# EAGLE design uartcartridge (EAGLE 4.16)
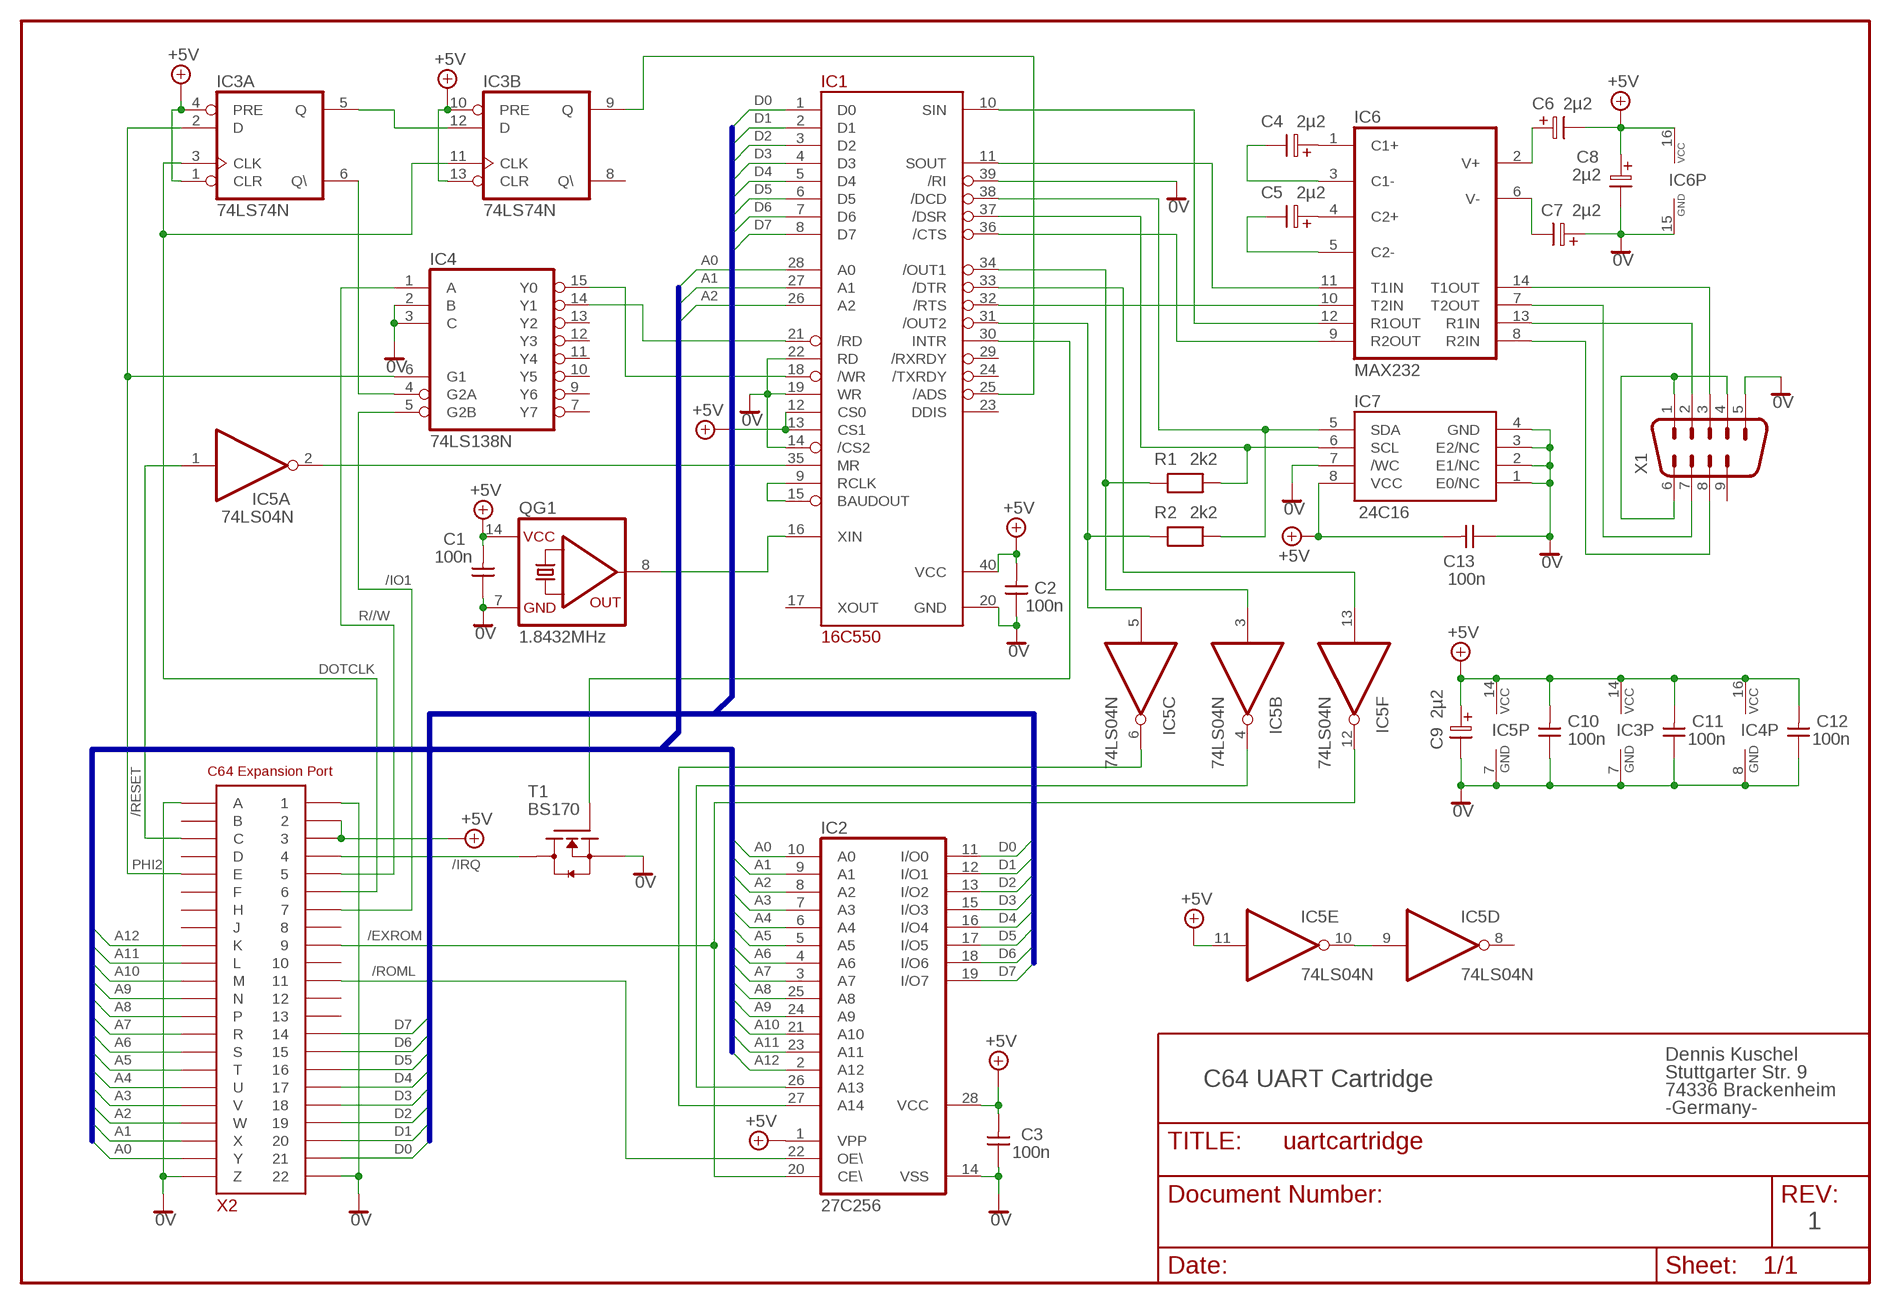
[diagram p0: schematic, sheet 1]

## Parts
C1  100n  CAPNP-5  [C-5]
C2  100n  CAPNP-5  [C-5]
C3  100n  CAPNP-5  [C-5]
C4  2µ2  ELC-2,5  [ES-2,5]
C5  2µ2  ELC-2,5  [ES-2,5]
C6  2µ2  ELC-2,5  [ES-2,5]
C7  2µ2  ELC-2,5  [ES-2,5]
C8  2µ2  ELC-2,5  [ES-2,5]
C9  2µ2  ELC-2,5  [ES-2,5]
C10  100n  CAPNP-5  [C-5]
C11  100n  CAPNP-5  [C-5]
C12  100n  CAPNP-5  [C-5]
C13  100n  CAPNP-5  [C-5]
IC1  16C550  [DIL40]
IC2  27C256  27C256AG  [DIL28-6]
IC3  74LS74N  [DIL14]
IC4  74LS138N  [DIL16]
IC5  74LS04N  [DIL14]
IC6  MAX232  [DIL16]
IC7  24C16  [DIL8]
QG1  1.8432MHz  QG5860  [DIL14S]
R1  2k2  RESEU-7,5  [R-7,5]
R2  2k2  RESEU-7,5  [R-7,5]
T1  BS170  BS170B  [TO92-]
X1  M09D  [M09D]
X2  CARTRIDGE-SUBD9  [EXPBOARD-SER]

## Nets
0V: C1.1 C2.1 C3.1 C7.1 C8.2 C9.2 C10.1 C11.1 C12.1 C13.1 IC1.14(/CS2) IC1.19(WR) IC1.20(GND) IC1.22(RD) IC1.39(/RI) IC2.14(VSS) IC3.7(P:GND) IC4.2(B) IC4.3(C) IC4.8(GND) IC5.7(P:GND) IC6.15(GND) IC7.1(E0/NC) IC7.2(E1/NC) IC7.3(E2/NC) IC7.4(GND) IC7.7(/WC) QG1.7(GND) T1.1(S) X1.5 X2.P$1 X2.P$22 X2.P$23(A) X2.P$44(Z)
+5V: C1.2 C2.2 C3.2 C6.2 C8.1 C9.1 C10.2 C11.2 C12.2 C13.2 IC1.12(CS0) IC1.13(CS1) IC1.40(VCC) IC2.1(VPP) IC2.28(VCC) IC3.1(A:CLR) IC3.4(A:PRE) IC3.10(B:PRE) IC3.13(B:CLR) IC3.14(P:VCC) IC4.16(VCC) IC5.11(E:I) IC5.14(P:VCC) IC6.16(VCC) IC7.8(VCC) QG1.14(VCC) X2.P$2 X2.P$3
/EXROM: IC2.20(CE\) IC5.12(F:O) X2.P$9
/IO1: IC4.5(G2B) X2.P$7
/IRQ: T1.3(D) X2.P$4
/RESET: IC5.1(A:I) X2.P$25(C)
/ROML: IC2.22(OE\) X2.P$11
A0: IC1.28(A0) IC2.10(A0) X2.P$43(Y)
A1: IC1.27(A1) IC2.9(A1) X2.P$42(X)
A2: IC1.26(A2) IC2.8(A2) X2.P$41(W)
A3: IC2.7(A3) X2.P$40(V)
A4: IC2.6(A4) X2.P$39(U)
A5: IC2.5(A5) X2.P$38(T)
A6: IC2.4(A6) X2.P$37(S)
A7: IC2.3(A7) X2.P$36(R)
A8: IC2.25(A8) X2.P$35(P)
A9: IC2.24(A9) X2.P$34(N)
A10: IC2.21(A10) X2.P$33(M)
A11: IC2.23(A11) X2.P$32(L)
A12: IC2.2(A12) X2.P$31(K)
CTS: IC6.8(R2IN) X1.8
D0: IC1.1(D0) IC2.11(I/O0) X2.P$21
D1: IC1.2(D1) IC2.12(I/O1) X2.P$20
D2: IC1.3(D2) IC2.13(I/O2) X2.P$19
D3: IC1.4(D3) IC2.15(I/O3) X2.P$18
D4: IC1.5(D4) IC2.16(I/O4) X2.P$17
D5: IC1.6(D5) IC2.17(I/O5) X2.P$16
D6: IC1.7(D6) IC2.18(I/O6) X2.P$15
D7: IC1.8(D7) IC2.19(I/O7) X2.P$14
DOTCLK: IC3.3(A:CLK) IC3.11(B:CLK) X2.P$6
N$1: IC3.5(A:Q) IC3.12(B:D)
N$2: IC1.25(/ADS) IC3.9(B:Q)
N$3: IC3.6(A:Q\) IC4.4(G2A)
N$4: IC1.21(/RD) IC4.14(Y1)
N$5: IC1.18(/WR) IC4.15(Y0)
N$6: IC5.9(D:I) IC5.10(E:O)
N$7: IC1.33(/DTR) IC5.13(F:I)
N$8: IC1.9(RCLK) IC1.15(BAUDOUT)
N$9: IC1.16(XIN) QG1.8(OUT)
N$10: IC1.34(/OUT1) IC5.3(B:I) R1.1
N$11: IC1.35(MR) IC5.2(A:O)
N$12: IC1.31(/OUT2) IC5.5(C:I) R2.1
N$13: IC2.26(A13) IC5.4(B:O)
N$14: IC2.27(A14) IC5.6(C:O)
N$15: C4.1 IC6.1(C1+)
N$16: IC1.30(INTR) T1.2(G)
N$17: C5.1 IC6.4(C2+)
N$18: C7.2 IC6.6(V-)
N$19: C6.1 IC6.2(V+)
N$20: C4.2 IC6.3(C1-)
N$21: C5.2 IC6.5(C2-)
N$22: IC1.10(SIN) IC6.12(R1OUT)
N$23: IC1.11(SOUT) IC6.11(T1IN)
N$24: IC1.32(/RTS) IC6.10(T2IN)
N$25: IC1.36(/CTS) IC6.9(R2OUT)
N$26: X1.1 X1.4 X1.6
N$27: IC1.37(/DSR) IC7.6(SCL) R1.2
N$29: IC1.38(/DCD) IC7.5(SDA) R2.2
PHI2: IC3.2(A:D) IC4.6(G1) X2.P$27(E)
R//W: IC4.1(A) X2.P$5
RTS: IC6.7(T2OUT) X1.7
RXD: IC6.13(R1IN) X1.2
TXD: IC6.14(T1OUT) X1.3
Unconnected: IC1.17(XOUT) IC1.23(DDIS) IC1.24(/TXRDY) IC1.29(/RXRDY) IC3.8(B:Q\) IC4.7(Y7) IC4.9(Y6) IC4.10(Y5) IC4.11(Y4) IC4.12(Y3) IC4.13(Y2) IC5.8(D:O) X1.9 X2.P$8 X2.P$10 X2.P$12 X2.P$13 X2.P$24(B) X2.P$26(D) X2.P$28(F) X2.P$29(H) X2.P$30(J)

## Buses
D[0..7]
A[0..12]

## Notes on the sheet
- C64 Expansion Port
- Dennis Kuschel
- Stuttgarter Str. 9
- C64 UART Cartridge
- 74336 Brackenheim
- -Germany-
- 1

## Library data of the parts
C1-C3 C10-C13 = discrete-my:CAPNP-5
C4-C9 = discrete-my:ELC-2,5
IC1 = UART:16C550: UART 16C550
IC2 = memory:27C256AG: MEMORY
IC3 = 74ttl:74*74: Dual D type positive edge triggered FLIP FLOP, preset and clear
IC4 = 74ttl:74*138: 3-line to 8-line DECODER/DEMULTIPLEXER
IC5 = 74ttl:74*04: Hex INVERTER
IC6 = maxim:MAX232: RS232 TRANSEIVER
IC7 = miscic:24C16
QG1 = crystal:QG5860: CRYSTAL RESONATOR
R1 R2 = discrete-my:RESEU-7,5
T1 = transistor-fet:BS170
X1 = con-subd_my:M09: SUB-D
X2 = c64:CARTRIDGE-SUBD9

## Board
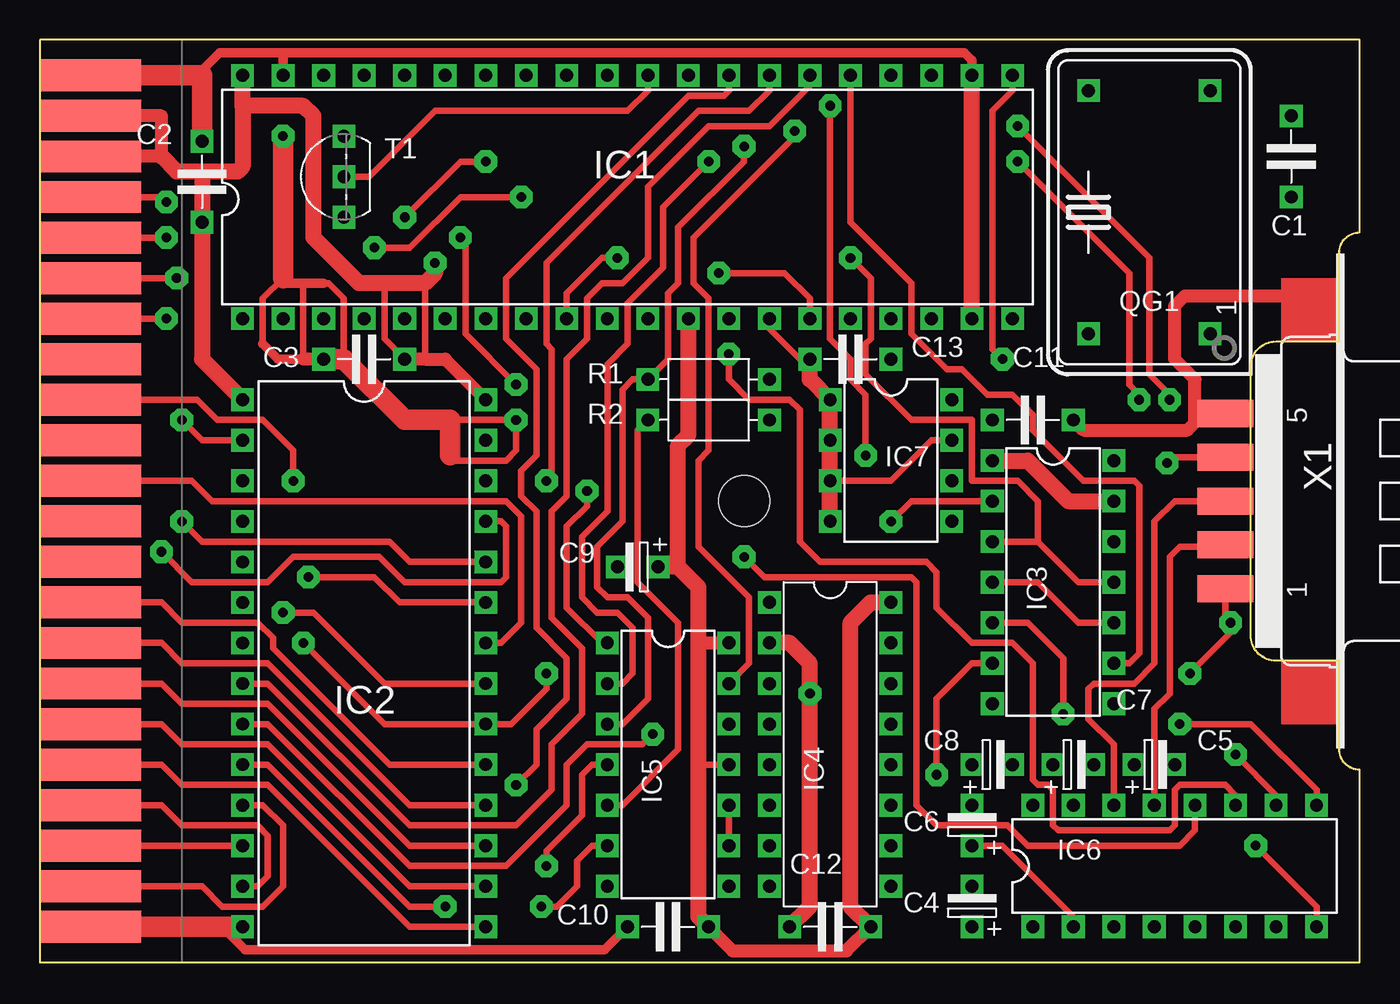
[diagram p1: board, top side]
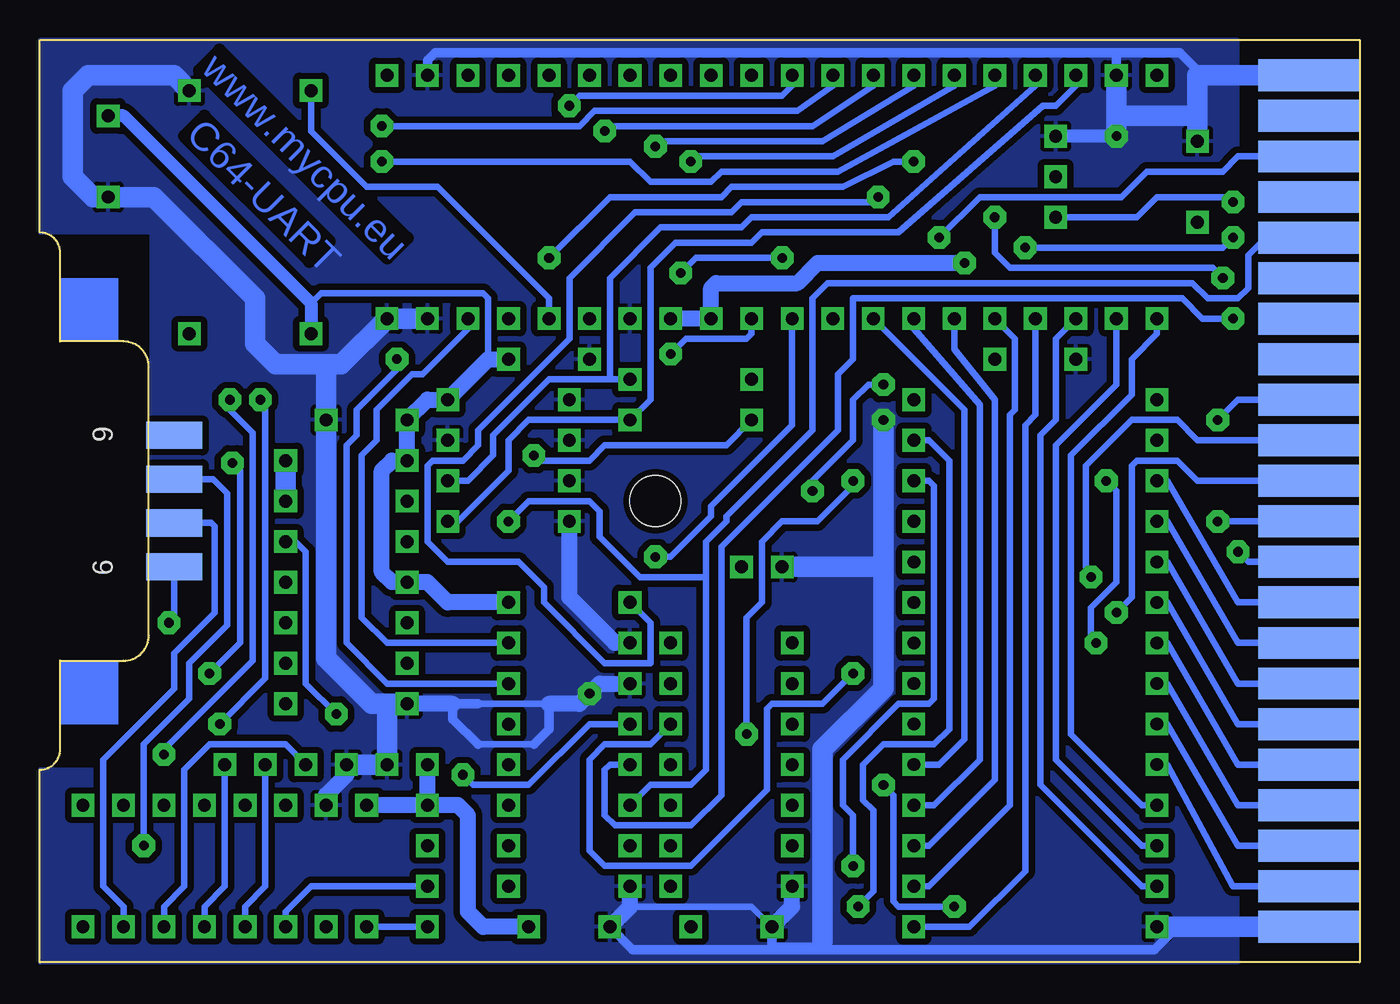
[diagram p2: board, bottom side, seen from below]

Size 82.71 x 57.78 mm. Coordinates in mm from the lower left corner, seen from the top.
Copper layers (1*16): Top 0.035mm / dielectric 1.5mm / Bottom 0.035mm
Design rules "default": minimum track width 10mil, minimum drill 0.6mm, track to track 10mil, track to pad 8mil, pad to pad 8mil, via to via 8mil, smd to smd 8mil, copper to edge 0mil, drill to drill 8mil, minimum pad ring 10mil, minimum via ring 8mil, stop-mask expansion 4mil, vias tented up to drill 0mil, thermal gap 10mil

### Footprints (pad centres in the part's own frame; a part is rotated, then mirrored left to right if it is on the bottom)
C-5 = drill 0.813 pad 1.422 square: 1 -2.54,0; 2 2.54,0
ES-2,5 = drill 0.813 pad 1.422 square: 1 -1.27,0; 2 1.27,0
DIL40 = drill 0.813 pad 1.422 square: 1 -24.13,-7.62; 2 -21.59,-7.62; 3 -19.05,-7.62; 4 -16.51,-7.62; 5 -13.97,-7.62; 6 -11.43,-7.62; 7 -8.89,-7.62; 8 -6.35,-7.62; 9 -3.81,-7.62; 10 -1.27,-7.62; 11 1.27,-7.62; 12 3.81,-7.62; 13 6.35,-7.62; 14 8.89,-7.62; 15 11.43,-7.62; 16 13.97,-7.62; 17 16.51,-7.62; 18 19.05,-7.62; 19 21.59,-7.62; 20 24.13,-7.62; 21 24.13,7.62; 22 21.59,7.62; 23 19.05,7.62; 24 16.51,7.62; 25 13.97,7.62; 26 11.43,7.62; 27 8.89,7.62; 28 6.35,7.62; 29 3.81,7.62; 30 1.27,7.62; 31 -1.27,7.62; 32 -3.81,7.62; 33 -6.35,7.62; 34 -8.89,7.62; 35 -11.43,7.62; 36 -13.97,7.62; 37 -16.51,7.62; 38 -19.05,7.62; 39 -21.59,7.62; 40 -24.13,7.62
DIL28-6 = drill 0.8 pad 1.422 square: 1 -16.51,-7.62; 2 -13.97,-7.62; 3 -11.43,-7.62; 4 -8.89,-7.62; 5 -6.35,-7.62; 6 -3.81,-7.62; 7 -1.27,-7.62; 8 1.27,-7.62; 9 3.81,-7.62; 10 6.35,-7.62; 11 8.89,-7.62; 12 11.43,-7.62; 13 13.97,-7.62; 14 16.51,-7.62; 15 16.51,7.62; 16 13.97,7.62; 17 11.43,7.62; 18 8.89,7.62; 19 6.35,7.62; 20 3.81,7.62; 21 1.27,7.62; 22 -1.27,7.62; 23 -3.81,7.62; 24 -6.35,7.62; 25 -8.89,7.62; 26 -11.43,7.62; 27 -13.97,7.62; 28 -16.51,7.62
DIL14 = drill 0.813 pad 1.422 square: 1 -7.62,-3.81; 2 -5.08,-3.81; 3 -2.54,-3.81; 4 0,-3.81; 5 2.54,-3.81; 6 5.08,-3.81; 7 7.62,-3.81; 8 7.62,3.81; 9 5.08,3.81; 10 2.54,3.81; 11 0,3.81; 12 -2.54,3.81; 13 -5.08,3.81; 14 -7.62,3.81
DIL16 = drill 0.813 pad 1.422 square: 1 -8.89,-3.81; 2 -6.35,-3.81; 3 -3.81,-3.81; 4 -1.27,-3.81; 5 1.27,-3.81; 6 3.81,-3.81; 7 6.35,-3.81; 8 8.89,-3.81; 9 8.89,3.81; 10 6.35,3.81; 11 3.81,3.81; 12 1.27,3.81; 13 -1.27,3.81; 14 -3.81,3.81; 15 -6.35,3.81; 16 -8.89,3.81
DIL16' = drill 0.8 pad 1.422 square: 1 -8.89,-3.81; 2 -6.35,-3.81; 3 -3.81,-3.81; 4 -1.27,-3.81; 5 1.27,-3.81; 6 3.81,-3.81; 7 6.35,-3.81; 8 8.89,-3.81; 9 8.89,3.81; 10 6.35,3.81; 11 3.81,3.81; 12 1.27,3.81; 13 -1.27,3.81; 14 -3.81,3.81; 15 -6.35,3.81; 16 -8.89,3.81
DIL8 = drill 0.8 pad 1.422 square: 1 -3.81,-3.81; 2 -1.27,-3.81; 3 1.27,-3.81; 4 3.81,-3.81; 5 3.81,3.81; 6 1.27,3.81; 7 -1.27,3.81; 8 -3.81,3.81
DIL14S = drill 0.813 pad 1.422 square: 1 -7.62,-3.81; 7 7.62,-3.81; 8 7.62,3.81; 14 -7.62,3.81
R-7,5 = drill 0.813 pad 1.422 square: 1 -3.81,0; 2 3.81,0
TO92- = drill 0.8 pad 1.422 square: 1 2.54,0; 2 0,0; 3 -2.54,0
M09D = smd 1.7 x 3.5: 1 5.486,-6.045; 2 2.743,-6.045; 3 0,-6.045; 4 -2.743,-6.045; 5 -5.486,-6.045 | smd 1.7 x 3.5 bottom: 6 4.115,-6.045; 7 1.372,-6.045; 8 -1.372,-6.045; 9 -4.115,-6.045
EXPBOARD-SER = smd 6.35 x 2: P$1 3.175,55.88; P$2 3.175,53.34; P$3 3.175,50.8; P$4 3.175,48.26; P$5 3.175,45.72; P$6 3.175,43.18; P$7 3.175,40.64; P$8 3.175,38.1; P$9 3.175,35.56; P$10 3.175,33.02; P$11 3.175,30.48; P$12 3.175,27.94; P$13 3.175,25.4; P$14 3.175,22.86; P$15 3.175,20.32; P$16 3.175,17.78; P$17 3.175,15.24; P$18 3.175,12.7; P$19 3.175,10.16; P$20 3.175,7.62; P$21 3.175,5.08; P$22 3.175,2.54 | smd 6.35 x 2 bottom: P$23 3.175,55.88; P$24 3.175,53.34; P$25 3.175,50.8; P$26 3.175,48.26; P$27 3.175,45.72; P$28 3.175,43.18; P$29 3.175,40.64; P$30 3.175,38.1; P$31 3.175,35.56; P$32 3.175,33.02; P$33 3.175,30.48; P$34 3.175,27.94; P$35 3.175,25.4; P$36 3.175,22.86; P$37 3.175,20.32; P$38 3.175,17.78; P$39 3.175,15.24; P$40 3.175,12.7; P$41 3.175,10.16; P$42 3.175,7.62; P$43 3.175,5.08; P$44 3.175,2.54 | hole 3.2: 44.133,29.21

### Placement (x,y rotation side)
C1  78.42,50.48 90 top
C2  10.16,48.89 270 top
C3  20.32,37.78 0 top
C4  58.42,3.49 90 top
C5  69.85,12.38 0 top
C6  58.42,8.57 90 top
C7  64.77,12.38 0 top
C8  59.69,12.38 0 top
C9  37.47,24.77 180 top
C10  39.37,2.22 0 top
C11  62.23,33.97 180 top
C12  49.53,2.22 0 top
C13  50.8,37.78 0 top
IC1  36.83,47.94 0 top
IC2  20.32,18.73 270 top
IC3  63.5,23.81 270 top
IC4  49.53,13.65 270 top
IC5  39.37,12.38 270 top
IC6  MAX232  [DIL16']  71.12,6.03 0 top
IC7  53.34,31.43 270 top
QG1  69.53,46.99 90 top
R1  41.91,36.51 0 top
R2  41.91,33.97 0 top
T1  19.05,49.21 90 top
X1  80.33,28.89 270 top
X2  0,-0.32 0 top

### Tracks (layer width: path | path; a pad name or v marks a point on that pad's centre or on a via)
0V  (via drill 0.6 pad 1.42)
  Top 0.406: 15.24,42.54 15.24,42.86 13.97,41.59 13.97,38.74 | 16.51,37.78 16.51,42.54 | 25.72,31.75 25.72,31.43 29.21,31.43 29.84,32.07 v29.84,33.97 25.72,33.97 | C13.1 47.62,37.78 45.72,39.69 IC1.14 | IC7.7 55.88,32.7 53.34,30.16 IC7.3 | 19.05,37.78 19.05,41.59 18.1,42.54 17.78,42.54
  Top 0.61: 16.51,37.78 14.92,37.78 13.97,38.74 | C10.1 35.4,0.79 12.86,0.79 11.43,2.22 | 15.24,56.99 57.94,56.99 58.42,56.52 IC1.22 | IC1.39 15.24,56.99 | 15.24,56.99 11.27,56.99 10.16,55.88 10.16,55.56 | 17.78,42.54 16.51,42.54 15.24,42.54
  Top 0.813: C3.1 16.51,37.78 | X1.5 72.48,34.38 72.39,34.29 | 72.39,34.29 72.39,33.81 71.91,33.34 65.41,33.34 C11.1 | 72.39,34.29 72.39,36.51 71.12,37.78 71.12,41.12 71.75,41.75 79.53,41.75
  Top 1.016: C12.1 48.26,3.49 v48.26,16.83 48.26,18.73 46.99,20 IC4.2 | IC1.19 IC1.22 | IC7.4 IC7.3 IC7.2 IC7.1 48.26,36.51 C13.1
  Top 1.27: 15.24,42.86 v15.24,51.75 | C3.1 19.05,37.78 22.86,33.97 25.72,33.97 25.72,31.75 | X2.P$22 11.43,2.22 IC2.14 | X2.P$1 10.16,55.56 C2.1
  Bottom 0.406: 50.8,16.19 55.24,16.19 | 51.75,13.65 55.24,13.65 | C10.1 38.1,3.49 45.88,3.49
  Bottom 0.61: C10.1 36.83,0.95 | 36.83,0.95 36.83,0.79 | C12.1 45.56,0.79 36.83,0.79 | 33.66,0.79 12.86,0.79 11.43,2.22 | 33.66,0.79 33.66,0.95 | 33.66,0.95 33.66,1.27 | 36.83,0.95 33.66,0.95 | 55.24,16.19 56.83,16.19 56.83,15.24 55.24,13.65 | 51.75,13.65 50.8,14.6 50.8,16.19 | IC1.22 58.42,56.52 57.94,56.99 15.24,56.99 | 33.66,0.79 36.83,0.79 | IC1.39 15.24,56.99 | 15.24,56.99 11.27,56.99 10.16,55.88 10.16,55.56
  Bottom 0.813: v15.24,51.75 T1.1
  Bottom 1.016: IC5.7 35.56,3.49 C10.1 | IC4.8 45.72,3.49 C12.1 | C7.1 63.5,11.75 64.77,10.48 IC6.15 | IC4.2 46.67,20 49.53,22.86 IC7.4 | 50.8,16.19 48.9,16.19 v48.26,16.83 47.62,17.46 IC4.3 | 56.83,16.19 IC3.7
  Bottom 1.27: 15.24,53.02 10.16,53.02 | 15.24,53.02 IC1.39 | v15.24,51.75 15.24,53.02 | 33.66,1.27 33.66,13.33 29.84,17.14 29.84,24.76 | 29.84,24.76 v29.84,33.97 | 10.16,53.02 C2.1 | 29.84,24.76 C9.2 | C7.1 C8.2 60.96,16.19 | IC3.7 60.96,16.19 | IC1.19 IC1.20 63.82,37.46 64.77,37.46 | 64.77,37.46 67.94,37.46 69.22,38.74 69.22,41.59 75.56,47.94 C1.1 79.38,47.94 80.64,49.21 80.64,54.61 79.69,55.56 74.3,55.56 QG1.7 | 60.96,16.19 61.91,16.19 64.77,19.05 C11.1 64.77,37.46 | IC2.14 11.43,2.22 X2.P$22 | X2.P$1 10.16,55.56 10.16,53.02
  pour Bottom (isolate 0.406): 7.62,57.78 82.71,57.78 82.71,45.72 75.72,45.72 75.72,12.06 82.71,12.06 82.71,0 7.62,0
+5V  (via drill 0.6 pad 1.42)
  Top 0.406: 21.59,42.54 21.59,39.05 C3.2 | 24.13,42.54 24.13,37.78 | 41.27,12.38 IC5.11 | IC3.10 65.09,21.27 62.55,23.81 IC3.4
  Top 0.813: IC2.28 25.4,37.78 24.13,37.78 C3.2 | C10.2 43.42,0.71 50.56,0.71 C12.2 | 41.27,20 IC5.14 | X2.P$2 7.62,53.02 7.62,50.48 X2.P$3
  Top 1.016: 10.16,49.53 8.57,49.53 7.62,50.48 | 12.7,53.66 16.51,53.66 17.14,53.02 17.14,45.4 20,42.54 21.59,42.54 24.13,42.54 24.77,43.18 v24.77,43.82 | C10.2 41.27,2.86 41.27,12.38 41.27,20 41.27,23.49 40.01,24.76 | C12.2 50.8,3.49 50.8,21.27 52.07,22.54 IC4.16 | 10.16,49.53 12.38,49.53 12.7,49.85 12.7,53.66 | 10.16,49.53 C2.2 10.16,37.78 IC2.1 | 40.01,24.76 40.01,32.39 40.64,33.02 IC1.12 | 12.7,53.66 IC1.40 | 40.01,24.76 C9.1 | IC3.13 64.45,28.89 61.91,31.43 IC3.1
  Bottom 0.406: 65.72,41.28 65.09,41.91 54.93,41.91 54.61,41.59 54.61,37.78
  Bottom 0.813: QG1.14 65.72,41.28 77.47,53.02 C1.2
  Bottom 1.016: v24.77,43.82 33.97,43.82 35.24,42.54 40.32,42.54 40.64,42.23 IC1.12 IC1.13 | C11.2 58.42,35.24 IC7.8 54.61,37.78 C13.2 | IC3.1 C11.2 | C6.2 IC6.16 | C6.2 56.52,9.84 55.88,9.21 55.88,3.18 54.93,2.22 C12.2 | C6.2 C8.1 | IC4.16 57.15,22.54 58.42,23.81 IC3.4 60.64,23.81 61.28,24.45 61.28,30.8 60.64,31.43 IC3.1 | IC3.1 C11.2
  Bottom 1.27: IC3.13 IC3.14
/EXROM  (via drill 0.6 pad 1.42)
  Top 0.406: v15.88,30.16 15.88,32.07 13.97,33.97 11.11,33.97 9.84,35.24 X2.P$9 | v16.51,20 21.59,14.92 IC2.20 29.53,14.92 31.75,17.14 v31.75,18.1
  Bottom 0.406: v16.51,20 16.83,20.32 16.83,22.23 15.24,23.81 15.24,29.53 v15.88,30.16 | v31.75,18.1 33.66,16.19 36.83,16.19 37.15,15.87 37.15,10.8 41.91,6.03 47.31,6.03 48.26,6.99 48.26,12.7 47.31,13.65 44.45,13.65 IC5.12
/IO1  (via drill 0.6 pad 1.42)
  Top 0.406: X2.P$7 v7.94,40.32
  Bottom 0.406: v7.94,40.32 9.84,40.32 11.11,41.59 31.75,41.59 31.75,37.78 32.7,36.83 32.7,33.34 40.01,26.03 40.01,10.48 41.91,8.57 46.67,8.57 47.31,9.21 47.31,12.07 46.99,12.38 IC4.5
/IRQ  (via drill 0.6 pad 1.42)
  Top 0.406: v7.94,47.63 7.62,47.94 X2.P$4
  Bottom 0.406: v7.94,47.63 8.26,47.94 12.7,47.94 13.97,46.67 T1.3
/RESET  (via drill 0.6 pad 1.42)
  Top 0.406: IC5.1 35.24,20 33.02,22.23 33.02,27.3 34.29,28.57 v34.29,29.53 | v29.84,36.2 26.67,39.37 26.67,45.09 v26.35,45.4
  Bottom 0.406: v34.29,29.53 34.29,30.16 31.75,32.7 31.75,35.24 30.8,36.2 v29.84,36.2 | v26.35,45.4 23.81,47.94 14.92,47.94 13.34,49.53 8.57,49.53 7.62,50.48 X2.P$25
/ROML
  Top 0.406: IC2.22 28.89,20 30.16,21.27 30.16,27.94 29.21,28.89 10.79,28.89 9.53,30.16 X2.P$11
A0  (via drill 0.6 pad 1.42)
  Top 0.406: IC2.10 14.29,12.38 23.18,3.49 v25.4,3.49 | v29.84,11.11 31.11,12.38 31.11,14.6 33.02,16.51 33.02,19.05 31.11,20.96 31.11,28.26 30.16,29.21 30.16,30.8 31.11,31.75 31.11,37.15 29.21,39.05 29.21,42.86 40.64,54.29 42.86,54.29 43.18,54.61 IC1.28
  Bottom 0.406: IC2.10 12.06,12.38 7.94,4.76 X2.P$43 | v25.4,3.49 28.89,3.49 29.21,3.81 29.21,10.48 v29.84,11.11
A1  (via drill 0.6 pad 1.42)
  Top 0.406: IC2.9 14.29,14.92 23.18,6.03 29.21,6.03 33.02,9.84 33.02,12.38 34.29,13.65 37.78,13.65 v38.42,14.29 | v31.75,30.16 32.07,30.48 32.07,38.42 31.75,38.74 31.75,43.82 41.27,53.34 44.45,53.34 45.72,54.61 IC1.27
  Bottom 0.406: IC2.9 12.06,14.92 7.62,7.3 X2.P$42 | v38.42,14.29 38.42,21.59 37.47,22.54 37.47,26.35 36.2,27.62 33.97,27.62 31.75,29.85 v31.75,30.16
A2
  Top 0.406: IC2.8 14.29,17.46 23.18,8.57 29.84,8.57 32.07,10.8 32.07,13.65 33.97,15.56 33.97,19.69 32.07,21.59 32.07,28.26 33.02,29.21 33.02,37.78 34.29,39.05 34.29,41.59 35.24,42.54 36.51,42.54 38.1,44.13 38.1,48.58 41.91,52.39 45.72,52.39 48.26,54.93 IC1.26
  Bottom 0.406: IC2.8 12.06,17.46 7.62,9.84 X2.P$41
A3
  Bottom 0.406: IC2.7 12.06,20 7.62,12.38 X2.P$40
A4
  Bottom 0.406: IC2.6 12.06,22.54 7.62,14.92 X2.P$39
A5
  Bottom 0.406: IC2.5 12.06,25.08 7.62,17.46 X2.P$38
A6
  Bottom 0.406: IC2.4 12.06,27.62 7.62,20 X2.P$37
A7
  Bottom 0.406: IC2.3 12.06,30.16 7.62,22.54 X2.P$36
A8  (via drill 0.6 pad 1.42)
  Top 0.406: v7.62,25.72 9.53,23.81 14.29,23.81 15.88,25.4 21.27,25.4 22.86,23.81 28.89,23.81 29.21,24.13 29.21,27.3 28.89,27.62 IC2.25
  Bottom 0.406: v7.62,25.72 6.99,25.08 X2.P$35
A9  (via drill 0.6 pad 1.42)
  Top 0.406: IC2.24 23.18,25.08 21.91,26.35 10.16,26.35 v8.89,27.62
  Bottom 0.406: X2.P$34 v8.89,27.62
A10  (via drill 0.6 pad 1.42)
  Top 0.406: v15.24,21.91 17.14,21.91 21.59,17.46 IC2.21
  Bottom 0.406: v15.24,21.91 14.29,22.86 14.29,31.12 13.97,31.43 11.43,31.43 10.16,30.16 X2.P$33
A11  (via drill 0.6 pad 1.42)
  Top 0.406: IC2.23 22.54,22.54 20.95,24.13 v16.83,24.13
  Bottom 0.406: v16.83,24.13 17.14,24.76 17.14,31.12 14.29,33.97 11.43,33.97 10.16,32.7 X2.P$32
A12  (via drill 0.6 pad 1.42)
  Top 0.406: v8.89,33.97 10.16,32.7 IC2.2
  Bottom 0.406: v8.89,33.97 7.62,35.24 X2.P$31
CTS  (via drill 0.6 pad 1.42)
  Top 0.406: v76.2,7.3 80.01,3.49 IC6.8
  Bottom 0.406: X1.8 71.86,30.26 70.96,29.37 70.96,21.11 73.34,18.73 73.34,16.51 76.2,13.65 v76.2,7.3
D0
  Top 0.406: IC2.11 13.97,9.84 15.24,8.57 15.24,4.76 13.97,3.49 11.43,3.49 10.16,4.76 X2.P$21
  Bottom 0.406: IC1.1 12.7,39.37 14.29,37.78 14.29,35.56 18.1,31.75 18.1,14.29 13.65,9.84 IC2.11
D1
  Top 0.406: X2.P$20 IC2.12
  Bottom 0.406: IC1.2 15.24,36.2 19.05,32.39 19.05,12.7 13.65,7.3 IC2.12
D2
  Top 0.406: IC2.13 13.65,4.76 14.29,5.4 14.29,7.94 13.65,8.57 8.89,8.57 7.62,9.84 X2.P$19
  Bottom 0.406: IC1.3 19.05,39.05 19.05,33.97 20,33.02 20,11.11 13.65,4.76 IC2.13
D3
  Top 0.406: IC2.15 23.18,2.22 14.29,11.11 8.89,11.11 7.62,12.38 X2.P$18
  Bottom 0.406: IC1.4 20.32,34.29 20.95,33.65 20.95,5.71 24.45,2.22 IC2.15
D4
  Top 0.406: IC2.16 23.18,4.76 14.29,13.65 8.89,13.65 7.62,14.92 X2.P$17
  Bottom 0.406: IC1.5 21.59,39.05 21.59,34.61 21.91,34.29 21.91,9.84 26.99,4.76 IC2.16
D5
  Top 0.406: IC2.17 23.18,7.3 14.29,16.19 8.89,16.19 7.62,17.46 X2.P$16
  Bottom 0.406: IC1.6 25.4,38.42 22.86,35.24 22.86,11.43 26.99,7.3 IC2.17
D6
  Top 0.406: IC2.18 23.18,9.84 14.29,18.73 8.89,18.73 7.62,20 X2.P$15
  Bottom 0.406: IC1.7 27.94,39.69 23.81,34.92 23.81,12.7 26.67,9.84 IC2.18
D7
  Top 0.406: IC2.19 21.91,12.38 14.61,19.69 14.61,20.32 13.65,21.27 8.89,21.27 7.62,22.54 X2.P$14
  Bottom 0.406: IC1.8 24.77,34.61 24.77,13.97 26.35,12.38 IC2.19
DOTCLK  (via drill 0.6 pad 1.42)
  Top 0.406: v22.86,46.67 26.35,50.17 v27.94,50.17 | 62.55,26.35 62.55,28.89 61.28,30.16 58.42,30.16 58.42,33.97 54.61,33.97 51.75,36.83 51.75,38.74 52.07,39.05 52.07,42.86 v50.8,44.13 | 62.55,26.35 IC3.3 | 62.55,26.35 65.09,23.81 IC3.11 | X2.P$6 v8.57,42.86
  Bottom 0.406: v8.57,42.86 9.21,43.5 21.91,43.5 22.86,44.45 v22.86,46.67 | v27.94,50.17 29.21,50.17 32.38,48.58 39.37,48.58 40.01,47.94 46.99,47.94 v50.8,44.13
N$1  (via drill 0.6 pad 1.42)
  Top 0.406: v64.14,15.56 64.14,19.05 61.91,21.27 IC3.5
  Bottom 0.406: IC3.12 66.67,26.35 66.04,25.72 66.04,17.46 v64.14,15.56
N$2
  Top 0.406: IC3.9 68.26,18.73 68.9,19.37 68.9,29.85 68.58,30.16 65.41,30.16 62.23,33.34 62.23,34.29 60.96,35.56 59.37,35.56 57.78,37.15 56.83,37.15 54.61,39.37 54.61,42.54 50.8,46.35 IC1.25
N$3  (via drill 0.6 pad 1.42)
  Top 0.406: v56.2,11.75 56.2,16.51 58.42,18.73 IC3.6
  Bottom 0.406: IC4.4 48.26,14.92 52.07,11.11 55.56,11.11 v56.2,11.75
N$4  (via drill 0.6 pad 1.42)
  Top 0.406: v60.33,37.78 59.69,38.42 59.69,53.34 60.96,54.61 IC1.21
  Bottom 0.406: IC4.14 60.96,17.46 63.5,20 63.5,32.39 62.87,33.02 62.87,34.61 60.33,37.15 v60.33,37.78
N$5
  Bottom 0.406: IC4.15 60.96,20 62.55,21.59 62.55,31.75 61.59,32.7 61.59,34.61 59.37,36.83 58.74,36.83 55.88,39.69 IC1.18
N$6
  Top 0.406: IC5.9 IC5.10
N$7  (via drill 0.6 pad 1.42)
  Top 0.406: v47.31,52.07 47.31,51.75 40.96,45.4 40.96,42.54 41.91,41.59 41.91,32.07 41.27,31.43 41.27,26.03 44.45,22.86 44.45,18.73 IC5.13
  Bottom 0.406: IC1.33 30.48,54.93 34.29,52.39 46.67,52.39 v47.31,52.07
N$8  (via drill 0.6 pad 1.42)
  Top 0.406: IC1.9 33.02,41.91 35.24,44.13 v36.2,44.13 | v42.55,43.18 46.67,43.18 48.26,41.59 IC1.15
  Bottom 0.406: v36.2,44.13 41.59,44.13 v42.55,43.18
N$9
  Bottom 0.406: IC1.16 50.8,41.59 57.78,48.58 62.23,48.58 65.72,52.07 QG1.8
N$10  (via drill 0.6 pad 1.42)
  Top 0.406: v44.13,51.12 44.13,50.17 40.01,46.04 40.01,42.54 39.37,41.91 39.37,37.78 R1.1 37.15,36.51 36.51,35.88 36.51,27.62 34.92,26.03 34.92,23.49 35.56,22.86 36.83,22.86 38.1,21.59 38.1,16.51 36.51,14.92 IC5.3
  Bottom 0.406: IC1.34 27.94,54.93 33.66,51.43 43.5,51.43 v44.13,51.12
N$11  (via drill 0.6 pad 1.42)
  Top 0.406: v41.91,50.17 39.05,47.31 39.05,43.5 36.83,41.28 36.83,38.74 35.56,37.46 35.56,28.26 33.97,26.67 33.97,22.86 34.92,21.91 36.2,21.91 37.15,20.96 37.15,18.1 36.51,17.46 IC5.2
  Bottom 0.406: IC1.35 25.4,54.93 33.02,50.48 41.59,50.48 v41.91,50.17
N$12  (via drill 0.6 pad 1.42)
  Top 0.406: v51.75,31.75 51.75,35.56 50.8,36.51 50.8,37.78 49.53,39.05 v49.53,53.66 | IC5.5 36.51,9.84 40.01,13.33 40.01,21.27 37.47,23.81 37.47,33.34 R2.1
  Bottom 0.406: IC1.31 35.56,54.93 36.2,54.29 48.9,54.29 v49.53,53.66 | R2.1 39.69,32.39 47.31,32.39 48.26,31.43 51.44,31.43 v51.75,31.75
N$13  (via drill 0.6 pad 1.42)
  Top 0.406: v31.75,6.03 31.75,6.99 33.97,9.21 33.97,11.75 34.61,12.38 IC5.4
  Bottom 0.406: IC2.26 26.99,30.16 26.67,29.85 26.67,16.51 26.99,16.19 28.89,16.19 32.38,12.7 32.38,9.84 31.75,9.21 v31.75,6.03
N$14  (via drill 0.6 pad 1.42)
  Top 0.406: v31.43,3.49 32.38,3.49 33.66,4.76 33.66,6.35 34.61,7.3 IC5.6
  Bottom 0.406: IC2.27 26.99,32.7 25.72,31.43 25.72,14.6 26.67,13.65 29.84,13.65 31.11,12.38 31.11,10.16 30.48,9.52 30.48,4.45 v31.43,3.49
N$15
  Bottom 0.406: C4.1 IC6.1
N$16
  Top 0.406: T1.2 20.64,49.21 24.77,53.34 36.83,53.34 38.1,54.61 IC1.30
N$17
  Bottom 0.406: C5.1 68.58,4.76 69.85,3.49 IC6.4
N$18
  Bottom 0.406: C7.2 67.31,13.65 72.07,13.65 73.66,12.07 73.66,4.76 74.93,3.49 IC6.6
N$19
  Top 0.406: IC6.2 64.77,2.86 60.33,7.3 C6.1
N$20
  Bottom 0.406: C4.2 65.72,4.76 67.31,3.18 IC6.3
N$21
  Bottom 0.406: C5.2 71.12,4.76 72.39,3.49 IC6.5
N$22  (via drill 0.6 pad 1.42)
  Top 0.406: v44.13,25.4 45.4,24.13 54.61,24.13 54.93,23.81 54.93,9.84 56.2,8.57 60.64,8.57 61.91,7.3 71.44,7.3 72.39,8.25 IC6.12
  Bottom 0.406: IC1.10 35.56,33.65 40.64,28.57 40.64,27.94 43.18,25.4 v44.13,25.4
N$23  (via drill 0.6 pad 1.42)
  Top 0.406: v43.18,38.1 43.18,36.51 44.45,35.24 46.99,35.24 47.62,34.61 47.62,26.35 48.9,25.08 55.56,25.08 56.2,24.45 56.2,22.23 58.42,20 60.96,20 62.23,18.73 62.23,11.43 62.55,11.11 63.18,11.11 63.5,10.8 63.5,8.57 63.82,8.25 70.8,8.25 71.12,8.57 71.12,10.8 71.44,11.11 74.3,11.11 74.93,10.48 IC6.11
  Bottom 0.406: IC1.11 38.1,39.37 38.42,39.05 42.23,39.05 v43.18,38.1
N$24  (via drill 0.6 pad 1.42)
  Top 0.406: v61.28,52.39 69.53,44.13 69.53,36.83 70.8,35.56 v70.8,35.24 | v74.93,13.02 77.47,10.48 IC6.10
  Bottom 0.406: IC1.32 33.02,54.93 35.24,53.34 47.94,53.34 48.9,52.39 v61.28,52.39 | v70.8,35.24 70.8,34.61 69.37,33.18 69.37,18.89 74.93,13.33 v74.93,13.02
N$25  (via drill 0.6 pad 1.42)
  Top 0.406: v61.28,50.17 68.26,43.18 68.26,36.2 68.9,35.56 v68.9,35.24 | v71.44,14.92 75.88,14.92 80.01,10.8 IC6.9
  Bottom 0.406: IC1.36 22.86,54.93 32.7,49.53 40.01,49.53 40.64,48.89 44.45,48.89 45.72,50.17 v61.28,50.17 | v68.9,35.24 68.58,34.92 68.58,17.78 v71.44,14.92
N$26  (via drill 0.6 pad 1.42)
  Top 0.406: X1.1 74.28,21.28 v74.61,21.27 74.61,20.64 v72.07,18.1 | X1.4 71.01,31.64 v70.64,31.27
  Bottom 0.406: X1.6 74.3,21.59 v74.61,21.27 | v70.64,31.27 70.17,30.8 70.17,20 v72.07,18.1
N$27
  Bottom 0.406: IC1.37 20.32,54.93 29.53,46.67 38.1,46.67 38.73,46.04 43.81,46.04 46.99,42.86 46.99,36.51 | 46.99,36.51 R1.2 | 46.99,36.51 50.8,36.51 54.29,33.02 54.29,31.75 55.88,30.16 IC7.6
N$29
  Bottom 0.406: IC1.38 17.78,54.93 19.05,53.66 19.84,53.66 28.89,45.72 37.47,45.72 38.1,45.09 42.86,45.09 44.45,43.5 44.45,35.24 R2.2 52.07,33.97 53.34,32.7 53.34,30.8 56.52,27.62 IC7.5
PHI2  (via drill 0.6 pad 1.42)
  Top 0.406: v53.34,27.62 54.61,28.89 IC3.2
  Bottom 0.406: 40.96,24.13 40.96,12.07 41.91,11.11 44.45,11.11 IC4.6 | 40.96,24.13 40.96,26.35 39.69,27.62 39.69,27.94 34.29,33.34 34.29,41.59 33.34,42.54 10.48,42.54 9.53,41.59 7.62,41.59 6.99,42.23 6.99,44.29 6.19,45.09 X2.P$27 | 40.96,24.13 45.09,24.13 47.62,26.67 47.62,28.26 48.26,28.89 52.07,28.89 v53.34,27.62
R//W  (via drill 0.6 pad 1.42)
  Top 0.406: v20.95,44.77 23.18,44.77 26.35,47.94 v30.16,47.94 | X2.P$5 v7.94,45.4
  Bottom 0.406: v7.94,45.4 8.57,44.77 v20.95,44.77 | v30.16,47.94 30.48,47.63 38.73,47.63 39.37,46.99 45.4,46.99 49.53,42.86 49.53,39.05 55.24,33.34 55.24,32.39 56.2,31.43 58.1,31.43 58.42,31.12 58.42,26.35 57.15,25.08 52.7,25.08 51.12,23.49 51.12,22.54 47.31,18.73 44.45,18.73 44.45,21.27 IC4.1
RTS
  Bottom 0.406: X1.7 71.97,27.52 71.75,27.3 71.75,21.91 74.3,19.37 74.3,17.14 78.74,12.7 78.74,4.76 77.47,3.49 IC6.7
RXD
  Top 0.406: IC6.13 69.85,15.87 70.8,16.83 70.8,25.4 71.44,26.03 75.25,26.03 75.23,26.05 X1.2
TXD
  Top 0.406: IC6.14 67.31,13.65 65.72,15.24 65.72,17.14 66.04,17.46 68.58,17.46 69.85,18.73 69.85,27.62 71.12,28.89 X1.3 75.25,28.89
(copper drawn outside any net)
  shapes: Bottom area x2, Top area x2

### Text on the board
Bottom: www.mycpu.eu | C64-UART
